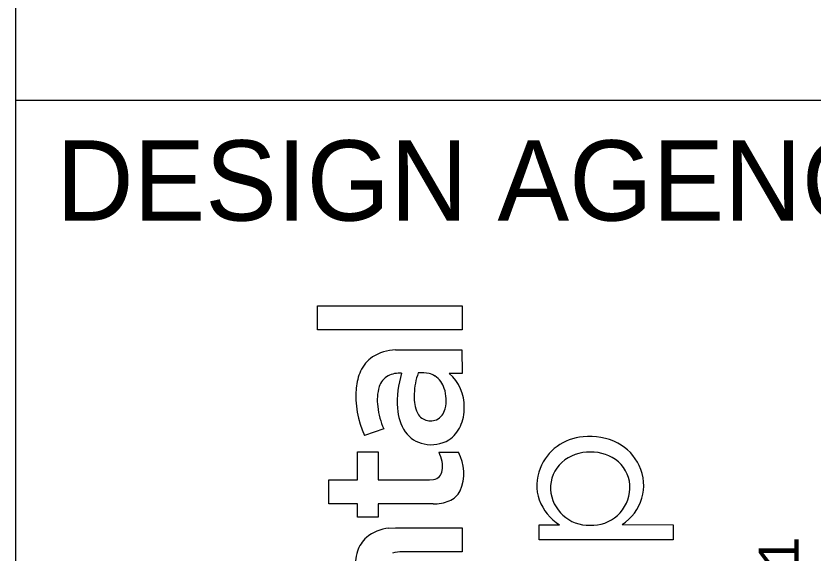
# Model space of a CAD drawing. Extents: x -4.9 to 34, y -1.2 to 22.
# Drawn here: x 32 to 32.993, y 4.436 to 5.105 of the extents above; entities that cross this region are included whole.
import ezdxf

# ---------------------------------------------------------------- set-up
doc = ezdxf.new("R2010")
doc.units = 0
doc.layers.add('SH_Border', color=7, linetype='Continuous')
doc.layers.add('SH_Data', color=7, linetype='Continuous')

msp = doc.modelspace()

# ---------------------------------------------------------------- linework, layer by layer
at = {"layer": 'SH_Border'}
for p, q in [((32, 0.5), (32, 21.5)), ((32, 5), (33.5, 5))]:
    msp.add_line(p, q, dxfattribs=at)
at = {"layer": 'SH_Data'}
for p, q in [((32.37557, 4.71411), (32.37557, 4.74397)), ((32.37557, 4.74397), (32.55571, 4.74397)), ((32.55571, 4.74397), (32.55571, 4.71411)), ((32.55571, 4.71411), (32.37557, 4.71411)), ((32.47265, 4.68899), (32.55553, 4.68918)), ((32.55553, 4.68918), (32.55571, 4.65956)), ((32.55571, 4.65956), (32.53971, 4.65956)), ((32.45818, 4.59045), (32.43431, 4.58233)), ((32.42542, 4.52705), (32.42548, 4.56209)), ((32.42548, 4.56209), (32.45108, 4.56209)), ((32.45108, 4.56209), (32.45117, 4.52705)), ((32.52695, 4.56159), (32.5511, 4.56159)), ((32.51498, 4.52705), (32.52005, 4.52749)), ((32.38964, 4.52701), (32.42542, 4.52705)), ((32.38964, 4.49719), (32.38964, 4.52701)), ((32.45117, 4.52705), (32.51498, 4.52705)), ((32.42542, 4.49717), (32.38964, 4.49719)), ((32.42542, 4.48067), (32.42542, 4.49717)), ((32.51969, 4.49718), (32.45108, 4.49715)), ((32.45108, 4.49715), (32.45108, 4.48066)), ((32.45108, 4.48066), (32.42542, 4.48067)), ((32.65152, 4.47113), (32.67709, 4.47115)), ((32.65152, 4.45215), (32.65152, 4.47113)), ((32.75491, 4.47132), (32.81858, 4.47108)), ((32.81858, 4.47108), (32.81843, 4.45215)), ((32.46439, 4.46686), (32.47289, 4.46732)), ((32.47289, 4.46732), (32.55571, 4.46732)), ((32.55571, 4.46732), (32.55571, 4.43753)), ((32.81843, 4.45215), (32.65152, 4.45215)), ((32.55571, 4.43753), (32.4814, 4.43746))]:
    msp.add_line(p, q, dxfattribs=at)
msp.add_lwpolyline([(32.37557, 4.71411), (32.37557, 4.74397), (32.55571, 4.74397), (32.55571, 4.71411)], close=True, dxfattribs=at)
for points in [[(32.47265, 4.68899), (32.55553, 4.68918), (32.55571, 4.65956)], [(32.55571, 4.65956), (32.53971, 4.65956)], [(32.45818, 4.59045), (32.43431, 4.58233)], [(32.51969, 4.49718), (32.45108, 4.49715), (32.45108, 4.48066), (32.42542, 4.48067), (32.42542, 4.49717), (32.38964, 4.49719), (32.38964, 4.52701), (32.42542, 4.52705), (32.42548, 4.56209), (32.45108, 4.56209), (32.45117, 4.52705), (32.51498, 4.52705), (32.52005, 4.52749)], [(32.52695, 4.56159), (32.5511, 4.56159)], [(32.75491, 4.47132), (32.81858, 4.47108), (32.81843, 4.45215), (32.65152, 4.45215)], [(32.65152, 4.45215), (32.65152, 4.47113), (32.67709, 4.47115)], [(32.46439, 4.46686), (32.47289, 4.46732), (32.55571, 4.46732), (32.55571, 4.43753), (32.4814, 4.43746)]]:
    msp.add_lwpolyline(points, dxfattribs=at)
for centre, radius, start, end in [((32.47452, 4.63256), 0.05646, 91.89422, 122.63175), ((32.47452, 4.63256), 0.05646, 91.89422, 122.63175), ((32.46847, 4.64467), 0.04302, 124.53704, 155.65938), ((32.46847, 4.64467), 0.04302, 124.53704, 155.65938), ((32.48824, 4.63612), 0.06457, 155.9764, 175.31491), ((32.48824, 4.63612), 0.06457, 155.9764, 175.31491), ((32.47786, 4.62778), 0.03213, 85.38017, 116.62224), ((32.47786, 4.62778), 0.03213, 85.38017, 116.62224), ((32.58787, 4.62508), 0.1129, 162.08213, 184.52847), ((32.58787, 4.62508), 0.1129, 162.08213, 184.52847), ((32.58013, 4.63131), 0.08411, 159.83657, 178.03621), ((32.58013, 4.63131), 0.08411, 159.83657, 178.03621), ((32.50509, 4.60743), 0.05302, 79.66963, 94.23216), ((32.50509, 4.60743), 0.05302, 79.66963, 94.23216), ((32.50892, 4.63643), 0.02384, 56.89129, 76.21489), ((32.50892, 4.63643), 0.02384, 56.89129, 76.21489), ((32.50551, 4.61914), 0.05295, 358.07459, 49.76196), ((32.50551, 4.61914), 0.05295, 358.07459, 49.76196), ((32.47525, 4.6356), 0.024, 119.42515, 161.66285), ((32.47525, 4.6356), 0.024, 119.42515, 161.66285), ((32.5052, 4.63184), 0.02973, 17.59837, 55.72819), ((32.5052, 4.63184), 0.02973, 17.59837, 55.72819), ((32.53639, 4.63078), 0.113, 174.61011, 205.38987), ((32.53639, 4.63078), 0.113, 174.61011, 205.38987), ((32.50758, 4.62645), 0.05758, 163.13694, 188.16749), ((32.50758, 4.62645), 0.05758, 163.13694, 188.16749), ((32.4916, 4.6264), 0.04435, 345.94084, 18.99188), ((32.4916, 4.6264), 0.04435, 345.94084, 18.99188), ((32.54655, 4.6303), 0.05063, 175.59026, 199.88569), ((32.54655, 4.6303), 0.05063, 175.59026, 199.88569), ((32.54725, 4.62973), 0.09735, 186.75982, 203.79807), ((32.54725, 4.62973), 0.09735, 186.75982, 203.79807), ((32.50187, 4.61678), 0.05657, 336.01604, 0.59505), ((32.50187, 4.61678), 0.05657, 336.01604, 0.59505), ((32.53279, 4.61874), 0.05752, 182.56764, 213.71437), ((32.53279, 4.61874), 0.05752, 182.56764, 213.71437), ((32.51642, 4.61886), 0.01841, 198.28436, 293.30806), ((32.51642, 4.61886), 0.01841, 198.28436, 293.30806), ((32.51521, 4.61994), 0.01989, 295.28829, 347.46387), ((32.51521, 4.61994), 0.01989, 295.28829, 347.46387), ((32.51752, 4.60969), 0.03938, 303.44357, 336.18), ((32.51752, 4.60969), 0.03938, 303.44357, 336.18), ((32.51487, 4.60782), 0.03656, 215.06685, 259.81327), ((32.51487, 4.60782), 0.03656, 215.06685, 259.81327), ((32.71081, 4.51825), 0.06243, 93.98662, 158.31194), ((32.71081, 4.51825), 0.06243, 93.98662, 158.31194), ((32.71557, 4.5065), 0.07459, 62.68889, 97.01346), ((32.71557, 4.5065), 0.07459, 62.68889, 97.01346), ((32.51753, 4.6131), 0.04227, 257.52557, 300.88195), ((32.51753, 4.6131), 0.04227, 257.52557, 300.88195), ((32.72123, 4.51914), 0.06076, 25.06574, 61.96022), ((32.72123, 4.51914), 0.06076, 25.06574, 61.96022), ((32.48625, 4.54199), 0.04518, 10.15449, 25.72303), ((32.48625, 4.54199), 0.04518, 10.15449, 25.72303), ((32.50302, 4.53506), 0.05491, 336.58903, 28.89913), ((32.50302, 4.53506), 0.05491, 336.58903, 28.89913), ((32.71379, 4.51017), 0.05134, 87.89653, 131.18123), ((32.71379, 4.51017), 0.05134, 87.89653, 131.18123), ((32.7175, 4.51023), 0.05127, 49.90886, 92.03625), ((32.7175, 4.51023), 0.05127, 49.90886, 92.03625), ((32.49573, 4.54365), 0.03556, 351.91398, 10.20594), ((32.49573, 4.54365), 0.03556, 351.91398, 10.20594), ((32.7092, 4.51674), 0.04338, 132.32887, 182.09489), ((32.7092, 4.51674), 0.04338, 132.32887, 182.09489), ((32.72154, 4.51733), 0.04327, 358.04871, 47.94467), ((32.72154, 4.51733), 0.04327, 358.04871, 47.94467), ((32.51837, 4.54001), 0.01263, 277.61423, 353.79181), ((32.51837, 4.54001), 0.01263, 277.61423, 353.79181), ((32.70695, 4.52016), 0.05815, 158.65601, 198.17101), ((32.70695, 4.52016), 0.05815, 158.65601, 198.17101), ((32.7245, 4.52004), 0.05743, 301.97764, 25.64176), ((32.7245, 4.52004), 0.05743, 301.97764, 25.64176), ((32.52913, 4.52612), 0.02749, 292.68889, 332.05977), ((32.52913, 4.52612), 0.02749, 292.68889, 332.05977), ((32.71352, 4.51815), 0.04776, 183.59741, 271.7045), ((32.71352, 4.51815), 0.04776, 183.59741, 271.7045), ((32.71717, 4.51801), 0.04766, 267.31494, 357.4019), ((32.71717, 4.51801), 0.04766, 267.31494, 357.4019), ((32.52088, 4.54856), 0.05139, 268.67266, 291.52354), ((32.52088, 4.54856), 0.05139, 268.67266, 291.52354), ((32.7103, 4.52433), 0.0627, 200.83985, 238.01619), ((32.7103, 4.52433), 0.0627, 200.83985, 238.01619), ((32.46871, 4.41716), 0.04988, 94.97056, 130.22484), ((32.46871, 4.41716), 0.04988, 94.97056, 130.22484), ((32.46348, 4.42551), 0.04016, 132.22383, 161.68229), ((32.46348, 4.42551), 0.04016, 132.22383, 161.68229), ((32.47872, 4.42108), 0.05602, 162.27398, 187.79173), ((32.47872, 4.42108), 0.05602, 162.27398, 187.79173), ((32.48108, 4.39145), 0.04601, 89.60515, 105.33026), ((32.48108, 4.39145), 0.04601, 89.60515, 105.33026)]:
    msp.add_arc(centre, radius, start, end, dxfattribs=at)

# ---------------------------------------------------------------- texts
msp.add_text('DESIGN AGENCY', height=0.1, dxfattribs=at).set_placement((32.05, 4.85))
msp.add_text('450 GRANT ST., AKRON, OH  44311', height=0.0498462, rotation=90, dxfattribs=at).set_placement((32.97489, 3.33738))

doc.saveas('drawing.dxf')
